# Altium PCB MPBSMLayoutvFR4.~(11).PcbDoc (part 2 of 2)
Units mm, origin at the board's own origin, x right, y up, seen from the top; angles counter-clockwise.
Board outline 131.7 x 110.39 mm, 4 copper layers (Top Layer, Power, GroundPlane, Bottom Layer), stack 2.286 mm thick; 156 components, 77 nets, 429 pads, 117 vias.
Unrouted connection lines stored in the file: 25.
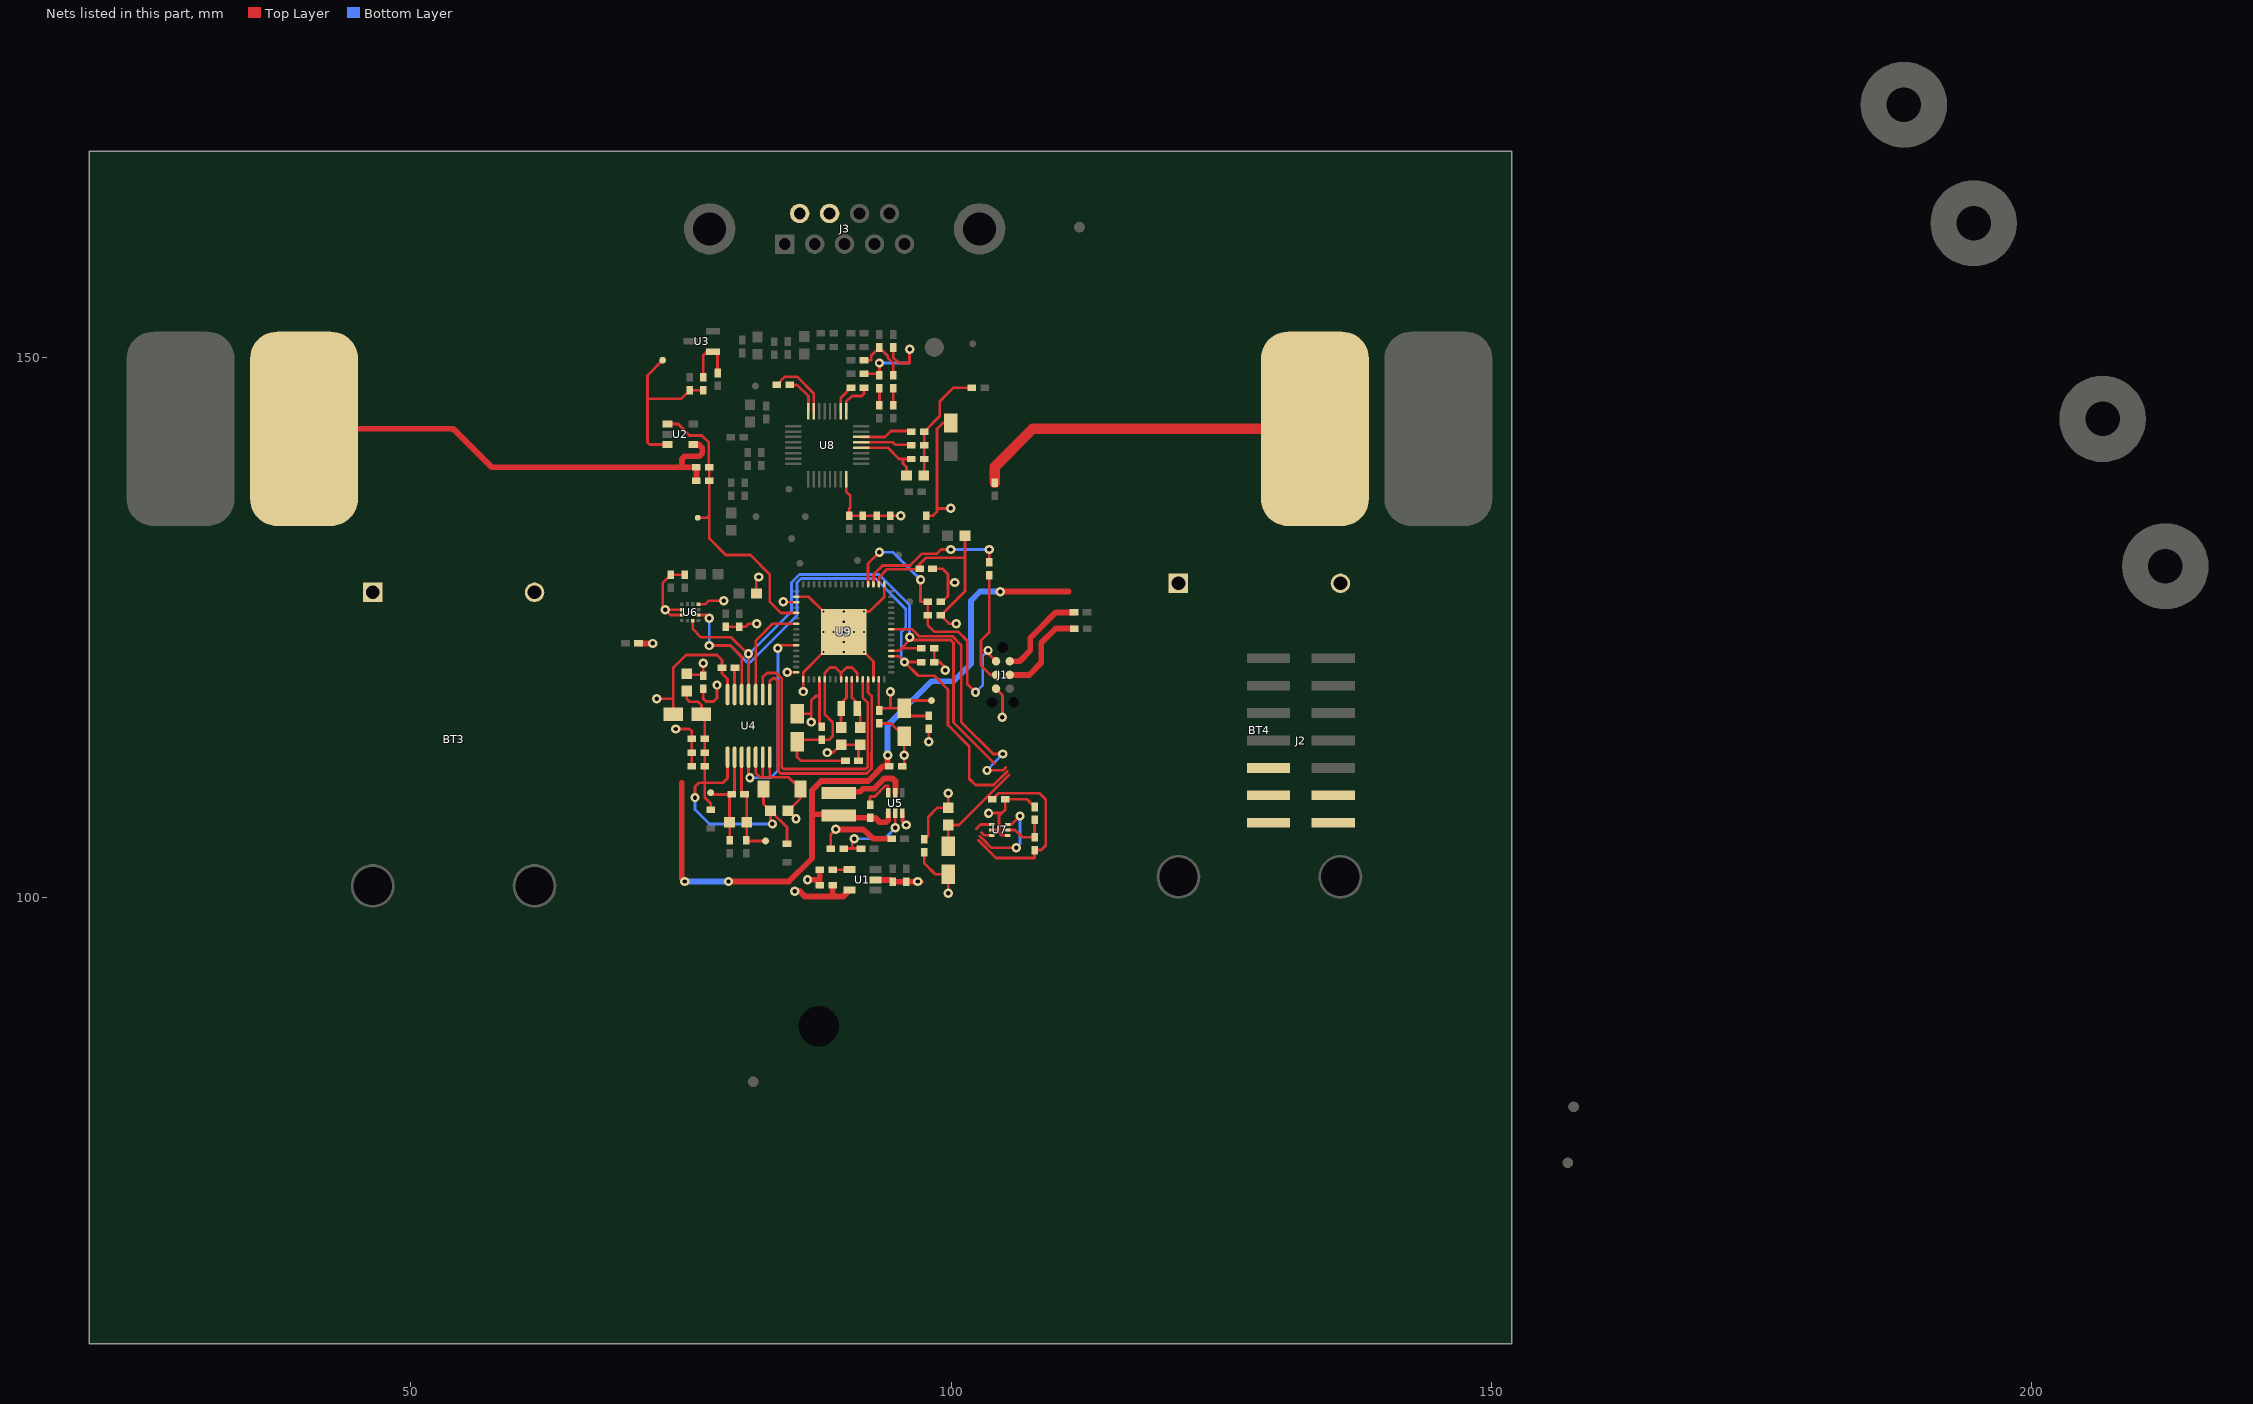
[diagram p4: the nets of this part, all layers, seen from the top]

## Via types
v1: diameter 0.864, hole 0.406, Top Layer to Bottom Layer, 104 vias
v2: diameter 0.5, hole 0.2, Top Layer to Bottom Layer, 13 vias

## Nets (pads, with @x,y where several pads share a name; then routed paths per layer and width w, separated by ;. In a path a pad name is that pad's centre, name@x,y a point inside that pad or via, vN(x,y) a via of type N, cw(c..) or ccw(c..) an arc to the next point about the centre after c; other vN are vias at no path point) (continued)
BOOST_INPUT: BT3.1 BT4.1 C34.1 L7.1 R16.1 U5.1 | length 73.3
  Top Layer w0.254: L7.1@89.586,107.681 L7.1@89.595,107.672 ; v1(94.132,113.132) v1@94.294,112.97
  Top Layer w0.5: 75.082,110.592 75.082,101.702 v1(75.336,101.448)
  Top Layer w0.54: v1(79.4,101.448) 84.988,101.448 87.122,103.581 87.122,109.906 87.96,110.744 92.304,110.744 93.675,112.116 C34.1@94.294,112.116 ; 87.122,107.696 L7.1@89.586,107.681 ; L7.1@89.806,107.35 R16.1@92.507,107.35 92.992,107.35 93.408,106.934 93.98,106.934 94.194,107.148 U5.1@94.194,107.762 ; C34.1@94.132,112.278 v1(94.132,113.132) ; v1(104.546,128.287) 110.895,128.287
  Bottom Layer w0.54: v1(75.336,101.448) v1(79.4,101.448) ; v1(94.132,113.132) 94.132,115.926 98.196,119.99 100.228,119.99 101.845,121.606 101.845,127.448 102.684,128.287 v1(104.546,128.287)
DVCC: 1.1 C1.1 C5.1 C6.1 C10.1 C14.1 C18.1 L1.1 L2.1 L3.1 L5.1 R1.1 R6.2 R31.1 R32.1 U1.5 U9.18 U9.35 U9.48 U9.63 | length 53
  Top Layer w0.254: L1.1@75.336,120.59 76.914,120.59 C10.1@76.938,120.613 ; C10.1@77.064,120.488 v1(77.064,121.666) ; L3.1@81.978,128.118 81.978,129.426 v1(82.194,129.642) ; v1@84.524,127.312 U9.35@85.668,127.312 ; v1(84.85,120.812) U9.48@85.668,120.812 ; U9.63@93.319,120.162 93.319,117.339 C6.1@93.37,117.288 ; U9.18@93.319,128.962 93.365,129.008 93.365,129.637 94.084,130.356 97.04,130.356 C18.1@97.088,130.404 97.088,130.82 97.688,131.42 101.244,131.42 ; C6.1@93.562,117.48 C1.1@95.656,117.48 ; 94.39,117.483 v1(94.39,119.027) ; C14.1@97.513,105.35 97.892,105.728 97.892,107.414 98.763,108.286 L2.1@99.753,108.286 v1(99.753,109.621) ; R1.1@97.942,116.78 96.356,116.78 C1.1@95.656,117.48 ; 1.1@98.196,118.212 96.388,118.212 C1.1@95.656,117.48 ; R32.1@98.45,123.038 R31.1@98.45,121.768 98.958,121.768 99.466,121.26 v1(99.466,121.006) ; v1(100.482,125.324) 99.812,125.324 R6.2@99.05,126.086 101.282,128.318 L5.1@101.282,133.452
  Top Layer w0.54: v1(85.522,100.559) v1@85.928,100.559 ; 85.954,100.584 86.462,100.076 89.048,100.076 ; C5.1@89.048,101.092 89.048,100.076 ; U1.5@90.596,100.65 90.022,100.076 89.048,100.076
  other v1: 84.48,127.356
EL_GSR1: C26.2 J3.7 R10.1 TP2.1 U2.4 | length 43.3
  Top Layer w0.254: U2.4@76.144,141.9 76.656,141.9
  Top Layer w0.54: TP2.1@40.107,143.358 53.924,143.358 57.48,139.802 R10.1@76.422,139.802 C26.2@76.422,138.532 ; 75.082,139.852 75.082,140.564 75.336,140.818 76.722,140.818 76.976,141.072 76.976,141.58 76.656,141.9
EL_GSR2: J3.6 R9.2 TP1.1 | length 32.6
  Top Layer w1: R9.2@104.038,138.37 104.038,139.827 107.569,143.358 TP1.1@133.68,143.358
GND: BT3.2 BT4.2 C1.2 C3.2 C4.2 C5.2 C6.2 C8.2 C9.2 C10.2 C11.2 C12.2 C13.2 C14.2 C15.2 C16.2 C17.2 C18.2 C19.2 C20.2 C21.2 C25.2 C27.2 C28.2 C29.1 C32.2 C33.2 C34.2 C35.2 C36.2 C37.2 C38.2 C41.2 C42.2 C58.2 C59.2 J1.6 J2.6 R2.1 R3.1 R17.1 U1.2 U4.5 U4.6 U4.7 U4.14 U5.3 U6.4 U6.8 U6.9 U7.2 U7.4 U8.24 U9.17 U9.34 U9.49 U9.62 U9.65 | length 145.9
  Top Layer w0.254: v1(72.746,118.364) 74.29,118.364 ; C9.2@74.29,116.942 74.29,118.364 ; v1(74.524,115.57) 75.794,115.57 76.006,115.357 C27.2@76.006,114.656 C11.2@76.006,113.386 C28.2@76.006,112.116 ; U6.9@75.069,126.111 74.041,126.111 v1(73.558,126.594) ; U6.8@75.069,126.611 73.575,126.611 v1(73.558,126.594) ; C37.2@75.336,129.847 C16.2@74.066,129.847 73.304,129.085 73.304,126.848 v1(73.558,126.594) ; U6.4@76.619,127.111 77.223,127.111 77.545,127.433 v1(78.965,127.433) ; C10.2@77.064,119.288 77.064,118.364 77.318,118.11 78.022,118.11 78.334,118.422 v1(78.334,119.634) ; C36.2@79.146,125.024 C17.2@80.416,125.024 80.972,125.024 81.272,125.324 v1(82.017,125.324) ; U4.14@79.311,118.764 79.311,120.193 78.8,120.704 C29.1@78.8,121.26 78.8,121.961 78.334,122.428 75.459,122.428 74.29,121.26 74.29,118.364 ; U4.5@81.911,112.964 81.911,111.484 82.296,111.1 83.21,111.1 ; 82.561,111.137 U4.6@82.561,112.964 ; U4.7@83.211,112.964 83.21,111.1 ; v1(85.645,107.266) 85.62,107.266 C33.2@84.895,107.991 86.049,109.145 C32.2@86.049,110.023 84.972,111.1 83.21,111.1 ; U9.34@85.668,127.812 86.818,127.812 v2(88.193,126.437) v2(90.068,124.562) ; v1(86.317,119.033) U9.49@86.317,120.162 86.317,120.811 v2(88.193,122.687) v2(90.068,124.562) ; v1(86.716,101.6) v1@86.728,101.613 ; v1(88.544,113.386) 89.09,113.386 89.814,114.11 C58.2@91.592,114.11 ; R17.1@88.868,104.496 88.868,105.812 v1(89.33,106.274) ; U8.24@90.294,138.704 90.294,137.544 90.676,137.162 90.676,136.099 90.576,135.999 C42.2@90.576,135.322 C41.2@91.846,135.322 C19.2@93.116,135.322 C20.2@94.386,135.322 v1@95.291,135.322 ; R2.1@91.43,112.624 C58.2@91.43,113.948 ; U9.62@92.819,120.162 92.819,121.811 v2(91.943,122.687) v2(90.068,124.562) ; C6.2@93.37,115.888 C6.2@93.37,116.088 94.448,116.088 C1.2@95.656,114.88 95.675,114.861 v1(95.675,113.132) 95.675,112.296 C34.2@95.494,112.116 C34.2@95.656,111.954 ; U9.17@93.819,128.962 93.819,127.805 92.451,126.437 v2(91.943,126.437) v2(90.068,124.562) ; C3.2@94.422,101.6 C3.2@94.594,101.428 ; v1(96.926,101.448) 96.926,101.194 v1@97.16,101.428 ; C14.2@97.513,104.15 97.513,103.147 98.538,102.122 C12.2@99.753,102.122 v1(99.753,100.374) ; C21.2@97.688,135.322 98.339,135.322 98.704,135.687 98.704,143.358 99.242,143.896 C15.2@99.974,143.896 C15.2@99.974,144.374 ; C18.2@98.288,130.404 99.212,130.404 99.72,129.896 99.72,129.134 ; 98.704,135.992 v1(99.974,135.992) ; C25.2@99.05,127.356 99.212,127.356 99.72,127.864 99.72,129.134 ; v1(100.355,129.134) 99.72,129.134 ; v1(103.475,107.783) 104.719,107.783 ; U7.2@103.754,106.221 104.423,106.221 ; J1.6@104.165,119.304 104.775,118.694 104.775,116.688 v1(104.75,116.662) ; U7.4@105.254,105.721 104.699,105.721 104.449,105.971 104.449,107.512 104.719,107.783 ; C38.2@107.731,108.352 107.015,109.068 C13.2@105.029,109.068 105.029,108.093 104.719,107.783
  Top Layer w0.354: U5.3@95.494,107.762 95.494,107.046 v1(95.86,106.68)
  Top Layer w0.54: R3.1@71.069,123.489 v1(72.371,123.489) ; v1@86.728,101.613 87.848,101.613 ; C5.2@87.848,101.092 87.848,101.613 ; C8.2@87.848,102.54 87.848,101.613 ; v1(89.33,106.274) 90.646,106.274 91.846,106.274 92.812,105.41 C35.2@94.548,105.41 ; U1.2@92.996,101.6 C3.2@94.422,101.6 ; C3.2@94.594,101.428 C4.2@95.864,101.428 v1@97.16,101.428
  other v1: 95.352,135.322
  other v2: 90.068,122.687 90.068,123.624 88.193,124.562 89.131,124.562 91.006,124.562 91.943,124.562 90.068,125.499 90.068,126.437
GSR_ANALOG_OUTPUT: 2.1 C26.1 R10.2 U2.1 U9.37 | length 26.9
  Top Layer w0.254: U2.1@73.744,143.8 74.751,143.8 75.802,142.748 76.92,142.748 77.58,142.088 77.58,140.14 77.622,140.098 R10.2@77.622,139.802 C26.1@77.622,138.532 77.622,135.23 ; 2.1@76.556,135.128 77.521,135.128 ; 77.521,135.23 77.622,135.23 ; U9.37@85.668,126.312 84.254,126.312 83.21,127.356 83.21,129.896 81.432,131.674 79.146,131.674 77.622,133.198 77.622,135.23
JTAG_TCK: J1.4 J2.4 R7.1 | length 10.4
  Top Layer w0.254: R7.1@103.53,129.804 103.53,124.511 102.768,123.749 102.768,121.463 103.657,120.574 J1.4@104.165,120.574
JTAG_TDO/TDI: C25.1 J1.2 J2.2 R6.1 U9.20 | length 28.1
  Top Layer w0.254: U9.20@92.319,128.962 92.319,130.876 v1(93.37,131.928) ; v1(97.18,129.388) 97.18,127.356 C25.1@97.85,127.356 R6.1@97.85,126.086 97.85,125.162 98.45,124.562 100.677,124.562 101.498,123.74 101.498,119.736 v1(102.26,118.974) ; v1(103.429,122.843) 103.429,122.58 J1.2@104.165,121.844
  Bottom Layer w0.254: v1(93.37,131.928) 94.64,131.928 v1(97.18,129.388) ; v1(102.26,118.974) 102.946,119.659 102.946,122.36 v1(103.429,122.843)
JTAG_TEST/SBWTCK: R7.2 U9.19 | length 13.7
  Top Layer w0.254: U9.19@92.819,128.962 92.819,129.852 93.676,130.71 96.216,130.71 97.307,131.801 98.703,131.801 99.084,132.182 v1(99.974,132.182) ; R7.2@103.53,131.004 v1(103.53,132.182)
  Bottom Layer w0.254: v1(99.974,132.182) v1(103.53,132.182)
JTAG_VCC_TARGET_IN: J1.3 J2.3 R5.1 | length 8.8
  Top Layer w0.54: J1.3@105.435,120.574 107.239,120.574 108.356,121.691 108.356,122.707 108.356,123.546 109.672,124.861 R5.1@111.408,124.861
JTAG_VCC_TOOL_OUT: J1.1 J2.1 R4.1 | length 8.5
  Top Layer w0.54: J1.1@105.435,121.844 106.35,121.844 107.34,122.834 107.34,124.003 109.703,126.365 R4.1@111.389,126.365
MSP_AVCC: C2.1 C7.1 R1.2 U9.52 | length 9.3
  Top Layer w0.254: C2.1@86.07,116.972 87.05,116.972 ; v1(87.05,116.21) 87.05,116.972 ; C7.1@87.818,115.982 87.818,118.618 ; U9.52@87.818,120.162 87.818,118.618 ; v1(97.942,114.402) R1.2@97.942,115.58 ; 87.05,116.972 87.05,118.191 87.478,118.618 87.818,118.618
MSP_AVSS: C2.2 C7.2 R2.2 U9.53 U9.56 U9.59 | length 20.5
  Top Layer w0.254: C2.2@85.75,114.372 85.75,112.979 86.106,112.624 R2.2@90.23,112.624 ; C2.2@85.942,114.564 C7.2@88.036,114.564 88.706,114.564 89.052,114.91 89.052,116.18 88.318,116.914 U9.53@88.318,120.162 88.318,120.779 88.798,121.26 89.306,121.26 89.81,120.756 ; U9.56@89.818,120.162 89.818,120.756 90.322,121.26 90.83,121.26 91.319,120.771 U9.59@91.319,120.162
MSP_LFXIN: C59.1 U9.57 Y1.1 | length 4.1
  Top Layer w0.254: C59.1@89.814,115.71 89.814,117.438 Y1.1@89.826,117.45 ; Y1.1@89.826,117.97 90.318,118.462 U9.57@90.318,120.162
MSP_LFXOUT: C58.1 U9.58 Y1.2 | length 4.3
  Top Layer w0.254: U9.58@90.819,120.162 90.819,118.477 Y1.2@91.326,117.97 ; Y1.2@91.326,117.45 91.592,117.184 C58.1@91.592,115.71
MSP_P1.0_INT: U4.10 U9.39 | length 9.4
  Top Layer w0.254: U4.10@81.911,118.764 81.911,123.749 ; 81.927,123.749 83.49,125.312 U9.39@85.668,125.312
MSP_P2.7_INT: U7.3 U9.9 | length 24.2
  Top Layer w0.254: U9.9@94.468,124.812 96.392,124.812 97.05,124.154 100.128,124.154 100.936,123.346 100.936,116.234 103.911,113.259 v1(104.775,113.259) ; 102.816,105.989 103.084,105.721 U7.3@103.754,105.721 ; v1@103.335,111.743 104.796,111.743 105.064,112.011
  Bottom Layer w0.254: v1(103.327,111.735) v1(104.775,113.259)
MSP_P4.0_INT: U4.9 U9.60 | length 28.4
  Top Layer w0.254: U4.9@82.561,118.764 82.561,120.356 82.956,120.752 83.823,120.752 84.326,120.248 84.326,112.016 84.48,111.862 92.1,111.862 92.285,112.046 92.285,113.506 92.294,113.516 92.294,114.704 92.285,114.713 92.285,115.106 92.294,115.116 92.294,116.304 92.285,116.313 92.285,118.027 91.819,118.493 U9.60@91.819,120.162
MSP_P4.1_INT: U4.8 U9.61 | length 27.8
  Top Layer w0.254: U4.8@83.211,118.764 83.211,119.99 83.464,120.244 83.718,120.244 83.972,119.99 83.972,111.718 84.236,111.454 92.2,111.454 ; 92.2,111.461 92.639,111.9 92.639,113.36 92.648,113.369 92.648,118.612 92.319,118.942 U9.61@92.319,120.162
MSP_P9.3_OUT: U4.4 U9.43 | length 18
  Top Layer w0.254: U4.4@81.261,112.964 81.261,111.169 v1(81.382,111.049) ; v1(83.972,123.038) 84.246,123.312 U9.43@85.668,123.312
  Bottom Layer w0.254: v1(81.382,111.049) 83.304,111.049 83.972,111.718 v1(83.972,123.038)
MSP_UCB0SCL_TMP103_SCL_RF430CL330HCPW_SCL: R32.2 U4.11 U6.12 U7.1 U9.5 | length 56.8
  Top Layer w0.254: U6.12@76.094,125.586 76.094,124.82 76.86,124.054 79.654,124.054 v1@81.211,122.497 ; U4.11@81.261,118.764 v1@81.261,122.447 ; U9.5@94.468,122.812 95.176,122.812 95.402,123.038 ; v1(96.164,124.054) v1@96.164,123.8 ; R32.2@97.088,123.038 95.402,123.038 ; 102.365,106.343 102.743,106.721 U7.1@103.754,106.721 ; 104.018,112.365 103.836,112.547 100.228,116.18 100.228,123.546 99.974,123.8 v1@96.164,123.8 ; 95.402,123.038 v1@96.164,123.8
  Bottom Layer w0.254: v1(81.252,122.539) 81.261,122.531 81.261,122.447 85.242,126.428 85.242,129.134 85.975,129.866 93.34,129.866 96.164,127.042 v1(96.164,124.054)
MSP_UCB0SDA_TMP103_SDA_RF430CL330HCPW_SDA: R31.2 U4.12 U6.2 U7.6 U9.4 | length 70.6
  Top Layer w0.254: U6.2@76.619,126.111 77.343,126.111 v1(77.622,125.832) ; v1(77.622,123.292) 79.568,123.292 80.627,122.233 80.627,118.78 U4.12@80.611,118.764 ; U9.4@94.468,122.312 95.148,122.312 v1(95.692,121.768) ; R31.2@97.25,121.768 v1(95.692,121.768) ; 102.669,105.635 102.972,105.332 102.98,105.332 103.742,104.57 v1(106.028,104.57) ; 105.211,111.657 103.943,110.388 102.26,110.388 101.689,110.96 101.689,113.957 99.72,115.926 99.72,119.228 98.45,120.498 96.962,120.498 v1(95.692,121.768) ; U7.6@105.254,106.721 105.588,106.721 v1(106.383,107.516)
  Bottom Layer w0.254: v1(77.622,125.832) v1(77.622,123.292) 79.568,123.292 81.092,121.768 81.432,121.768 85.75,126.086 85.75,129.134 86.129,129.512 92.992,129.512 95.81,126.694 95.81,124.97 95.402,124.562 95.402,122.058 v1(95.692,121.768) ; v1(106.028,104.57) 106.383,104.925 v1(106.383,107.516)
Net3_1: 3.1 R11.1 R12.2 U2.3 | length 15.6
  Top Layer w0.254: 71.896,146.152 75.033,146.152 R12.2@75.799,146.917 R11.1@77.069,146.917 ; 3.1@73.304,149.708 71.896,148.3 71.896,142.088 72.084,141.9 U2.3@73.744,141.9
Net4_1: 4.1 C30.1 C31.1 R13.1 U4.2 | length 9.9
  Top Layer w0.254: 4.1@77.745,109.676 77.906,109.515 C31.1@79.685,109.515 ; R13.1@79.523,105.255 79.523,106.903 C30.1@79.485,106.941 79.485,109.315 C31.1@79.685,109.515 ; U4.2@79.961,112.964 79.961,109.791 C31.1@79.685,109.515
Net5_1: 5.1 C30.2 C31.2 R14.1 U4.3 | length 9.9
  Top Layer w0.254: U4.3@80.611,112.964 80.611,109.788 C31.2@80.885,109.515 81.085,109.315 C30.2@81.085,106.941 81.085,105.293 81.181,105.197 5.1@83.079,105.197
NetC8_1: C8.1 U1.4 | length 1.6
  Top Layer w0.254: C8.1@89.043,102.54 89.053,102.55 U1.4@90.596,102.55
NetC29_2: C29.2 U4.13 | length 2.5
  Top Layer w0.254: U4.13@79.961,118.764 79.961,121.22 C29.2@80,121.26
NetC38_1: C38.1 R18.1 U7.5 | length 4.3
  Top Layer w0.254: U7.5@105.254,106.221 105.926,106.221 106.589,105.558 R18.1@107.731,105.558 C38.1@107.731,107.152
NetC43_1: C43.1 R19.2 R20.2 R21.2 R22.1 | length 10.9
  Top Layer w0.254: C43.1@97.526,139.094 R20.2@97.526,140.564 R21.2@97.526,141.834 97.526,141.876 R19.2@97.526,143.104 98.958,144.536 98.958,145.898 99.678,146.618 100.228,147.168 R22.1@101.914,147.168
NetC43_2: C43.2 R20.1 U8.28 | length 6.7
  Top Layer w0.254: U8.28@91.694,141.603 94.147,141.603 95.186,140.564 95.555,140.564 ; C43.2@95.872,139.04 95.872,139.818 95.555,140.135 95.555,140.564 ; R20.1@96.326,140.564 95.555,140.564
NetC45_1: C45.1 U8.2 | length 2.6
  Top Layer w0.254: U8.2@89.794,145.003 89.794,146.224 C45.1@90.738,147.168
NetC45_2: C45.2 U8.1 | length 3.4
  Top Layer w0.254: U8.1@90.294,145.003 90.294,145.87 90.83,146.406 91.732,146.406 91.938,146.612 C45.2@91.938,147.168
NetC46_2: C46.2 C48.2 C49.2 | length 10.4
  Top Layer w0.254: C46.2@91.938,148.45 C49.2@93.242,148.45 ; C49.2@93.37,148.322 v1(93.37,149.454) ; C48.2@94.64,150.886 94.646,150.88 94.646,149.967 95.16,149.454 96.164,149.454 v1(96.164,150.724)
  Bottom Layer w0.254: v1(93.37,149.454) 96.164,149.454 v1(96.164,150.724)
NetC47_1: C47.1 U8.8 | length 3.5
  Top Layer w0.254: C47.1@85.08,147.422 85.75,147.422 86.794,146.378 U8.8@86.794,145.003
NetC47_2: C47.2 U8.7 | length 6
  Top Layer w0.254: C47.2@83.88,147.422 84.642,148.184 85.75,148.184 87.294,146.64 U8.7@87.294,145.003
NetC49_1: C49.1 R26.1 | length 1.6
  Top Layer w0.254: R26.1@93.37,145.528 C49.1@93.37,147.122
NetC52_2: C52.2 C53.2 C54.2 | length 5.3
  Top Layer w0.254: C54.2@91.938,149.708 92.608,149.708 92.608,150.124 C52.2@93.37,150.886 94.132,150.124 94.132,149.962 94.64,149.454 C53.2@94.64,148.322
NetC53_1: C53.1 R27.1 | length 1.6
  Top Layer w0.254: R27.1@94.64,145.528 C53.1@94.64,147.122
NetL7_2: L7.2 U5.5 | length 5.5
  Top Layer w0.254: 92.913,110.033 92.913,110.084
  Top Layer w0.54: L7.2@91.034,109.752 91.566,109.752 91.846,110.033 92.913,110.033 ; 92.913,110.084 93.494,110.664 93.828,110.998 94.59,110.998 94.844,110.744 U5.5@94.844,109.662
NetR8_1: R8.1 R11.2 U3.1 | length 5.5
  Top Layer w0.254: R11.2@77.069,148.117 77.069,150.17 77.434,150.536 78.384,150.536 R8.1@78.384,148.53
NetR15_1: R15.1 R17.2 U5.2 | length 8.1
  Top Layer w0.254: R17.2@90.068,104.496 90.865,104.496 ; v1(91.034,105.41) 90.865,105.242 90.865,104.496 ; R15.1@91.662,104.496 90.865,104.496 ; v1(94.844,106.426) U5.2@94.844,107.762
  Bottom Layer w0.254: v1(91.034,105.41) 93.828,105.41 v1(94.844,106.426)
NetR16_2: R16.2 U5.6 | length 3.5
  Top Layer w0.254: R16.2@92.507,108.55 92.507,109.271 92.558,109.322 92.939,109.322 93.944,110.327 94.183,110.327 94.183,109.672 U5.6@94.194,109.662
NetR19_1: R19.1 U8.30 | length 4.9
  Top Layer w0.254: U8.30@91.694,142.603 93.886,142.603 94.428,143.146 R19.1@96.326,143.146
NetR21_1: R21.1 U8.29 | length 4.7
  Top Layer w0.254: U8.29@91.694,142.103 94.625,142.103 94.852,141.876 R21.1@96.326,141.876
RF430_DVCC: C9.1 C11.1 C27.1 C28.1 C32.1 C33.1 D1.1 D2.1 L1.2 U4.1 | length 34
  Top Layer w0.254: 75.54,118.512 75.54,118.338 75.786,118.092 76.574,118.092 76.89,117.775 C9.1@76.89,116.942 C9.1@77.114,117.166 ; v1(76.302,109.22) 76.302,110.236 76.657,110.592 77.201,110.592 ; C28.1@77.206,112.116 C11.1@77.206,113.386 C27.1@77.206,114.656 C9.1@77.206,116.626 ; C28.1@77.298,112.024 77.201,111.926 77.201,110.592 ; D1.1@77.745,108.079 77.745,108.691 77.201,109.235 77.201,110.592 ; U4.1@79.311,112.964 79.311,111.01 78.892,110.592 77.201,110.592 ; C32.1@82.649,110.023 82.649,108.637 C33.1@83.295,107.991 ; v1(83.464,106.782) 83.295,106.951 C33.1@83.295,107.991 ; D2.1@84.811,104.989 84.811,106.475 C33.1@83.295,107.991
  Bottom Layer w0.254: v1(76.302,109.22) 76.302,108.102 77.622,106.782 v1(83.464,106.782)
TMP_DVCC: C12.1 C13.1 L2.2 R18.2 | length 27
  Top Layer w0.254: C12.1@99.753,104.722 L2.2@99.753,106.686 100.74,106.686 105.358,111.303 ; 102.522,105.281 104.173,103.63 107.731,103.63 R18.2@107.731,104.358 108.355,104.358 108.766,104.768 108.766,109.049 108.197,109.618 104.379,109.618 C13.1@103.829,109.068
pads on no net: BT3.3 BT3.4 BT4.3 BT4.4 FID1.1 FID2.1 FID3.1 H1.0 H2.0 H3.0 H4.0 H5.1 H6.1 H7.1 H8.1 H9.0 H10.0 H11.0 H12.0 J1.5 J1.MH1 J1.MH2 J1.MH3 J2.5 J2.7 J2.8 J2.9 J2.10 J2.11 J2.12 J2.13 J2.14 J3.3 J3.5 J3.8 J3.9 U3.3 U6.10 U8.17 U9.1 U9.2 U9.3 U9.6 U9.7 U9.8 U9.10 U9.11 U9.12 U9.13 U9.15 U9.21 U9.22 U9.23 U9.24 U9.36 U9.40 U9.41 U9.42 U9.44 U9.45 U9.46 U9.47 U9.50 U9.51 U9.54 U9.55 U9.64
copper on no net: | length 0.5
  Top Layer w0.254: 104.496,124.206 v1(104.496,124.714)

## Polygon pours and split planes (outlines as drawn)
DVCC on Power (split plane): 102.385,142.288 102.385,131.727 101.75,131.092 78.641,131.092 78.006,131.727 78.006,133.144 79.2,134.338 93.116,134.338 93.166,134.348 93.208,134.376 98.288,139.456 98.316,139.498 98.326,139.548 98.326,142.796 98.735,143.205 101.468,143.205
DVCC on Power (split plane): 87.561,117.065 87.907,116.61 87.907,112.624 87.917,112.574 87.945,112.532 87.987,112.504 88.036,112.494 96.002,112.494 96.052,112.504 96.094,112.532 97.018,113.456 97.046,113.498 97.056,113.548 97.056,115.796 98.819,115.796 98.819,115.57 98.819,113.937 98.359,113.477 97.081,112.2 96.619,111.737 86.778,111.737 86.134,112.41 86.134,116.653 86.549,117.089
DVCC on Power (split plane): 90.701,154.534 90.66,146.998 81.941,147.043 81.94,147.043 81.916,147.038 81.891,147.033 81.87,147.019 81.849,147.006 81.849,147.005 81.835,146.984 81.821,146.964 81.821,146.963 81.816,146.939 81.811,146.914 81.811,143.104 81.821,143.054 81.849,143.012 81.891,142.984 81.94,142.974 86.637,142.974 86.637,141.201 83.464,141.201 83.415,141.191 83.373,141.163 83.345,141.121 83.335,141.072 83.335,135.359 77.193,135.359 77.193,139.09 77.183,139.14 77.155,139.182 74.958,141.379 74.958,145.59 77.975,148.607 79.114,148.607 79.138,148.612 79.163,148.616 79.163,148.617 79.184,148.631 79.205,148.644 79.205,148.645 79.219,148.665 79.233,148.686 79.233,148.687 79.238,148.711 79.243,148.736 79.275,154.658 90.701,154.658
DVCC on Power (split plane): 151.407,158.471 151.407,59.159 20.729,59.159 20.729,168.527 151.407,168.527
ADS_AVSS on GroundPlane (split plane): 151.407,158.471 151.407,128.806 102.136,128.806 102.136,137.008 102.126,137.057 102.098,137.099 102.056,137.127 102.006,137.137 98.958,137.137 98.909,137.127 98.867,137.099 98.839,137.057 98.829,137.008 98.829,135.765 96.497,135.765 96.497,136.398 96.487,136.448 96.459,136.49 96.417,136.518 96.368,136.527 89.428,136.527 89.413,136.524 89.398,136.524 89.389,136.52 89.379,136.518 89.366,136.509 89.352,136.503 77.682,127.993 20.729,128.018 20.729,168.527 151.407,168.527
GND on GroundPlane (split plane): 101.877,128.676 101.887,128.627 101.915,128.585 101.957,128.557 102.006,128.547 151.407,128.547 151.407,59.159 20.729,59.159 20.729,127.759 77.724,127.734 77.774,127.744 77.816,127.772 77.819,127.776 77.835,127.784 89.471,136.269 96.238,136.269 96.238,135.636 96.248,135.586 96.276,135.544 96.318,135.516 96.368,135.507 98.958,135.507 99.008,135.516 99.05,135.544 99.078,135.586 99.088,135.636 99.088,136.878 101.877,136.878

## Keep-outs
Keep-Out Layer:
  text ".Layer_Name" at 157.226,108.306 h1.52

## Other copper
Top Layer:
  text ".Layer_Name" at 157.226,156.566 h1.52
Bottom Layer:
  text ".Layer_Name" at 157.226,154.026 h1.52
  text "SVN:" at 49.695,114.91 h1.52 r90
  text ".VersionControl_RevNumber" at 49.695,107.823 h1.52 r90
  text "UL94V-0" at 55.728,69.774 h1.52 r90
Power (plane layer: these items are gaps in the copper):
  rectangle: 74.828,69.952 100.228,99.67
  lines w0.254: 98.948,115.57 98.948,115.926 ; 98.948,115.926 98.545,115.926 96.926,115.926 96.926,113.548 96.002,112.624 88.256,112.624 88.036,112.624 88.036,116.654 87.627,117.193 86.494,117.219 86.004,116.705 86.004,112.358 86.722,111.608 92.19,111.608 96.672,111.608 97.173,112.108 98.45,113.386 98.948,113.884 98.948,115.926 ; 74.828,141.326 77.064,139.09 77.064,135.23 81.237,135.23 83.464,135.23 83.464,141.072 86.766,141.072 86.766,143.104 81.94,143.104 81.94,146.914 90.788,146.868 90.83,154.534 90.83,154.788 79.146,154.788 79.114,148.736 77.921,148.736 74.828,145.644 74.828,141.326 ; 77.876,131.674 77.876,133.198 79.146,134.468 93.116,134.468 98.196,139.548 98.196,142.85 98.681,143.334 101.522,143.334 102.514,142.342 102.514,131.674 101.803,130.962 78.588,130.962 77.876,131.674
GroundPlane (plane layer: these items are gaps in the copper):
  rectangle: 74.828,69.952 100.228,99.67
  lines w0.254: 20.091,127.889 77.724,127.864 ; 77.758,127.888 89.428,136.398 96.368,136.398 96.368,135.636 98.958,135.636 98.958,137.008 102.006,137.008 102.006,128.676 151.765,128.676

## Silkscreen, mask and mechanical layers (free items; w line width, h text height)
Top Overlay:
  region: 96.368,77.724 96.368,85.344 93.828,85.344 93.828,77.724
  lines w1: 73.914,70.891 101.041,70.891 101.041,98.222 73.914,98.222 73.914,70.891
  lines w2: 20.98,133.325 44.78,133.325 150.292,133.325 ; 48.971,60.96 48.971,132.918 48.971,167.716 ; 125.679,61.646 125.679,167.157
  text "GSR" at 130.099,153.289 h4
  text "ECG" at 141.478,153.238 h4
  text "ECG" at 24.74,152.806 h4
  text "GSR" at 37.389,152.756 h4
  text "GND" at 46.634,131.318 h1.02
  text "VCC" at 60.147,129.845 h1.02
  text ".Layer_Name" at 157.226,128.626 h1.52
  text "JTAG" at 106.782,126.009 h1.02
  text "BAT" at 110.592,122.987 h1.02
  text "VCC" at 62.027,121.361 h1.02
  text "GND" at 46.888,121.158 h1.02
  text "FOR DEMO PURPOSES ONLY" at 76.53,94.259 h1.02
  text "MPBSM" at 80.112,91.44 h1.02
  text "REV A" at 80.112,89.916 h1.02
  text "TI" at 92.202,87.884 h1.52
  text "©" at 94.844,87.63 h2.67
  text ".CopyrightYear" at 85.192,77.724 h1.52
  text "MADE IN U.S." at 78.842,75.438 h1.52
  text "NFC Antenna" at 80.594,68.504 h2
  text "-" at 50.952,67.666 h1.52 r90
  text "Place phone here" at 52.959,62.84 h10
Bottom Overlay:
  text ".Layer_Name" at 157.226,126.086 h1.52
Top Paste:
  text ".Layer_Name" at 157.226,123.546 h1.52
Bottom Paste:
  text ".Layer_Name" at 157.226,121.006 h1.52
Top Solder:
  text ".Layer_Name" at 157.226,118.466 h1.52
  text ".Layer_Name" at 157.226,115.926 h1.52
Bottom Solder:
  text ".Layer_Name" at 157.226,113.386 h1.52
Drill Guide:
  text ".Layer_Name" at 157.226,110.846 h1.52
M1 Board Outline:
  lines w0.254: 75.336,58.257 101.625,58.257
  text ".Layer_Name" at 157.226,151.486 h1.52
M2 Board Dimensions:
  rectangle: 17.577,32.982 20.752,36.157
  rectangle: 20.752,29.807 30.277,32.982
  lines w0.178: 17.577,32.982 42.977,32.982 ; 20.752,29.807 20.752,36.157 ; 23.927,29.807 23.927,36.157 ; 30.277,29.807 30.277,36.157 ; 36.627,29.807 36.627,36.157 ; 17.577,29.807 42.977,29.807 42.977,36.157 17.577,36.157 17.577,29.807
  text ".Layer_Name" at 18.034,37.338 h1.52
M3 3D STEP Top:
  text ".Layer_Name" at 157.226,148.946 h1.52
M4 3D STEP Bottom:
  text ".Layer_Name" at 157.226,146.406 h1.52
M5 Assembly Top:
  lines w0.254: 10.16,16.607 177.8,16.607 ; 10.16,21.772 177.851,21.772 ; 10.16,26.937 10.16,11.443 111.887,11.443 177.851,11.443 177.851,26.937 10.173,26.937 10.173,11.443 50.19,11.443 ; 72.771,11.443 72.771,26.937 ; 104.953,21.772 104.953,26.937 ; 126.289,21.772 126.289,26.937 ; 142.088,11.278 142.088,16.43
  text "COMPONENTS MARKED 'DNP' SHOULD NOT BE POPULATED." at 46.876,32.144 h1.52
  text "ASSEMBLY VARIANT:" at 46.863,29.21 h1.52
  text ".VariantName" at 73.177,29.21 h1.52
  text "PCB VIEWED FROM TOP SIDE" at 11.773,23.58 h1.52
  text "BOARD #:" at 74.676,23.58 h1.52
  text ".PRJ_Number" at 88.532,23.58 h1.52
  text "REV:" at 109.982,23.58 h1.52
  text ".PCB_Rev" at 117.386,23.58 h1.52
  text "SVN REV:" at 131.267,23.58 h1.52
  text ".VersionControl_RevNumber" at 144.12,23.58 h1.52
  text "IGNORE ->" at 11.773,18.428 h1.52
  text "PLOT NAME =" at 11.773,13.199 h1.52
  text ".plot_File_Name" at 32.233,13.199 h1.52
  text "GENERATED    :" at 74.727,13.199 h1.52
  text ".Print_Date" at 96.812,13.199 h1.52
  text ".Print_Time" at 115.329,13.199 h1.52
  text "TEXAS INSTRUMENTS" at 147.447,13.199 h1.52
M6 Assembly Bottom:
  lines w0.254: 10.147,21.759 177.838,21.759 ; 10.198,16.595 177.838,16.595 ; 45.91,11.265 45.91,16.417 ; 61.709,21.759 61.709,26.924 ; 83.045,21.759 83.045,26.924 ; 115.227,11.43 115.227,26.924 ; 137.808,11.43 177.825,11.43 177.825,26.924 10.147,26.924 10.147,11.43 76.111,11.43 177.838,11.43 177.838,26.924
  text "COMPONENTS MARKED 'DNP' SHOULD NOT BE POPULATED." at 172.568,32.156 h1.52
  text ".VariantName" at 146.05,29.21 h1.52
  text "ASSEMBLY VARIANT:" at 172.441,29.21 h1.52
  text ".VersionControl_RevNumber" at 43.878,23.567 h1.52
  text "SVN REV:" at 56.731,23.567 h1.52
  text ".PCB_Rev" at 70.612,23.567 h1.52
  text "REV:" at 78.016,23.567 h1.52
  text ".PRJ_Number" at 99.466,23.567 h1.52
  text "BOARD #:" at 113.322,23.567 h1.52
  text "PCB VIEWED FROM BOTTOM SIDE" at 176.225,23.567 h1.52
  text "IGNORE ->" at 82.292,18.428 h1.52
  text "TEXAS INSTRUMENTS" at 40.551,13.187 h1.52
  text ".Print_Time" at 72.669,13.187 h1.52
  text ".Print_Date" at 91.186,13.187 h1.52
  text "GENERATED    :" at 113.271,13.187 h1.52
  text ".plot_File_Name" at 155.766,13.187 h1.52
  text "PLOT NAME =" at 176.225,13.187 h1.52
M9 Title Sheet:
  drawing of 57 lines, arcs and shapes, not listed
  text "1" at 36.369,243.091 h1.78
  text "2" at 99.758,243.091 h1.78
  text "3" at 162.988,243.091 h1.78
  text "4" at 226.657,243.091 h1.78
  text "5" at 290.131,243.091 h1.78
  text "6" at 353.758,243.091 h1.78
  text "A" at 6.998,214.058 h1.78
  text "A" at 382.918,214.058 h1.78
  text "B" at 6.998,153.606 h1.78
  text "B" at 382.918,153.606 h1.78
  text ".Layer_Name" at 157.226,143.866 h1.52
  text "C" at 6.998,93.281 h1.78
  text "C" at 382.918,93.281 h1.78
  text "PROJECT TITLE:" at 305.702,46.012 h1.14
  text ".PRJ_Title" at 306.972,42.626 h1.78
  text "DESIGNED FOR:" at 305.702,38.367 h1.14
  text ".PRJ_Customer" at 306.972,34.811 h1.78
  text "D" at 6.998,33.084 h1.78
  text "D" at 382.918,33.084 h1.78
  text "FILE NAME:" at 305.702,30.747 h1.14
  text ".PCB_File_Name_No_Path" at 306.972,27.699 h1.78
  text "Texas Instruments (TI) and/or its licensors do not warrant the accuracy or completeness of this specification" at 179.476,23.588 h1.14
  text "ENGINEER:" at 305.702,23.381 h1.14
  text "LAYOUT BY:" at 343.929,23.381 h1.14
  text "or any information contained therein. TI and/or its licensors do not warrant that this design will meet" at 178.334,20.726 h1.14
  text ".PRJ_Engineer" at 306.972,19.444 h1.78
  text ".PCB_Layout" at 345.211,19.444 h1.78
  text "the specifications, will be suitable for your application or fit for any particular purpose, or will operate in" at 178.334,17.865 h1.14
  text "ALTIUM DESIGNER VERSION:" at 343.929,15.507 h1.14
  text "an implementation. TI and/or its licensors do not warrant that the design is production worthy. You should" at 178.334,15.003 h1.14
  text "completely validate and test your design implementation to confirm the system functionality for your application." at 179.476,12.141 h1.14
  text ".print_Scale" at 306.972,12.12 h1.78
  text ".Application_BuildNumber" at 345.211,12.12 h1.78
  text "1" at 36.369,6.871 h1.78
  text "2" at 99.758,6.871 h1.78
  text "3" at 162.988,6.871 h1.78
  text "4" at 226.657,6.871 h1.78
  text "5" at 290.131,6.871 h1.78
  text "6" at 353.758,6.871 h1.78
M10 Fab Notes:
  drawing of 185 lines, arcs and shapes, not listed
  text "DESIGN INFORMATION" at 332.055,190.348 h1.52
  text "MIN. TRACK WIDTH:" at 315.683,185.776 h1.52
  text "8" at 343.527,185.776 h1.52
  text "MIL" at 347.458,185.776 h1.52
  text "MIN. CLEARANCE:" at 315.683,182.423 h1.52
  text "0.2" at 342.003,182.423 h1.52
  text "mm" at 347.458,182.423 h1.52
  text "MIN. VIA PAD SIZE:" at 315.683,179.07 h1.52
  text "24" at 342.766,179.07 h1.52
  text "MIL" at 347.458,179.07 h1.52
  text "0.05mm (2MIL)" at 333.336,175.471 h1.52
  text "MINIMUM ANNULAR RING" at 307.32,175.362 h1.52
  text "EXTERNAL" at 351.319,175.362 h1.52
  text "PER" at 312.4,172.364 h1.52
  text "IPC-D-275 CLASS 2 LEVEL C" at 317.988,172.364 h1.52
  text "MIL, HOLES" at 355.789,169.512 h1.52
  text "+/-" at 345.821,169.494 h1.52
  text "+/-" at 367.513,169.494 h1.52
  text "REGISTRATION TOLERANCES:" at 307.32,169.367 h1.52
  text "METAL" at 337.795,169.367 h1.52
  text "5" at 352.43,169.367 h1.52
  text "3" at 373.588,169.367 h1.52
  text "MIL" at 376.541,169.367 h1.52
  text "MATERIAL:" at 305.421,164.047 h1.52
  text "FR-4 High Tg" at 330.477,160.482 h1.52
  text "FR-408" at 316.115,160.265 h1.52
  text "X" at 326.579,160.265 h1.52
  text "OTHER" at 353.91,160.265 h1.52
  text "62 MIL (1.6mm) +/-10%" at 324.245,156.132 h1.52
  text "THICKNESS:" at 307.32,156.023 h1.52
  text "X" at 320.99,156.023 h1.52
  text "OTHER" at 356.882,156.023 h1.52
  text "TOLERANCE:" at 307.32,152.01 h1.52
  text "X" at 328.639,152.01 h1.52
  text "ANSI IPC-6012 TYPE 3 CLASS 2" at 333.387,152.01 h1.52
  text "OTHER +/-" at 333.387,148.047 h1.52
  text "BOW & TWIST:" at 307.32,144.06 h1.52
  text "X" at 328.639,144.06 h1.52
  text "ANSI IPC-6012 TYPE 3 CLASS 2" at 333.387,144.06 h1.52
  text ".Layer_Name" at 157.226,141.326 h1.52
  text "OTHER +/-" at 333.387,140.034 h1.52
  text "DRILLING:" at 305.421,136.516 h1.52
  text "REFERENCE:" at 307.32,133.544 h1.52
  text "X" at 323.785,133.544 h1.52
  text "AS SHOWN" at 328.535,133.544 h1.52
  text "X" at 346.671,133.544 h1.52
  text "NC_DRILL FILES" at 350.151,133.544 h1.52
  text "PTH MIN COPPER THICKNESS:" at 307.32,129.531 h1.52
  text "X" at 341.616,129.531 h1.52
  text "1MIL" at 345.096,129.531 h1.52
  text "OTHER" at 357.72,129.531 h1.52
  text "BOARD FINISH:" at 305.421,125.492 h1.52
  text "SILKSCREEN:" at 309.364,122.495 h1.52
  text "X" at 333.463,122.495 h1.52
  text "TOP" at 336.663,122.495 h1.52
  text "X" at 346.417,122.495 h1.52
  text "BOTTOM" at 349.643,122.495 h1.52
  text "SILKSCREEN COLOR:" at 310.634,118.26 h1.52
  text "X" at 333.436,118.253 h1.52
  text "WHITE" at 336.663,118.253 h1.52
  text "OTHER" at 349.643,118.253 h1.52
  text "SOLDER RESIST COLOR:" at 309.364,113.935 h1.52
  text "GREEN" at 327.011,109.892 h1.52
  text "BLUE" at 342.023,109.892 h1.52
  text "OTHER" at 355.688,109.892 h1.52
  text "X" at 323.785,109.644 h1.52
  text "IMMERSION GOLD (ENIG)" at 332.371,105.103 h1.52
  text "ENEPIG" at 366.344,105.02 h1.52
  text "SURFACE FINISH:" at 305.421,104.994 h1.52
  text "X" at 327.622,104.994 h1.52
  text "IMM. TIN/SILVER OR EQUIV" at 313.792,101.007 h1.52
  text "OTHER" at 350.151,101.007 h1.52
  text "ARRAY/PANEL:" at 305.421,96.46 h1.52
  text "CUT AND TRIM PER MECH LAYER 1" at 332.371,96.351 h1.52
  text "N.C. ROUTE" at 332.371,92.498 h1.52
  text "X" at 349.617,92.498 h1.52
  text "V. SCORE" at 354.367,92.498 h1.52
  text "CERTIFICATION:" at 305.421,89.018 h1.52
  text "MATERIALS AND WORKMANSHIP FOR ALL PCBS" at 323.836,89.018 h1.52
  text "TO MEET OR EXCEED THE REQUIREMENTS OF:" at 323.836,86.529 h1.52
  text "X" at 314.349,83.061 h1.52
  text "ANSI IPC-A-600F CLASS ->" at 317.88,83.061 h1.52
  text "X" at 359.512,83.061 h1.52
  text "2" at 362.533,83.061 h1.52
  text "1" at 354.532,83.023 h1.52
  text "3" at 371.525,83.023 h1.52
  text "X" at 314.402,79.01 h1.52
  text "UL 94V-0" at 317.88,79.01 h1.52
  text "X" at 335.026,79.01 h1.52
  text "RoHS" at 338.505,79.01 h1.52
  text "OTHER" at 354.873,79.01 h1.52
  text "PER ORDER" at 364.958,79.01 h1.52
  text "ADDITIONAL REQUIREMENTS:" at 305.193,75.302 h1.52
  text "MICROSECTION:" at 307.092,72.381 h1.52
  text "YES" at 330.098,72.381 h1.52
  text "REQUIRED" at 352.208,68.542 h1.52
  text "NONE" at 340.486,68.469 h1.52
  text "X" at 348.982,68.469 h1.52
  text "PER ORDER" at 367.245,68.469 h1.52
  text "BARE BOARD ELEC. TEST:" at 307.092,68.342 h1.52
  text "MANUFACTURER'S UL:" at 307.092,64.354 h1.52
  text "METAL" at 349.422,64.373 h1.52
  text "X" at 358.953,64.364 h1.52
  text "SILK" at 362.419,64.373 h1.52
  text "RAIL" at 336.702,64.245 h1.52
M11 Gerber Information:
  lines w0.254: 10.16,16.607 177.8,16.607 ; 10.16,21.772 177.851,21.772 ; 10.16,26.937 10.16,11.443 111.887,11.443 177.851,11.443 177.851,26.937 10.173,26.937 10.173,11.443 50.19,11.443 ; 72.771,11.443 72.771,26.937 ; 104.953,21.772 104.953,26.937 ; 126.289,21.772 126.289,26.937 ; 142.088,11.278 142.088,16.43
  text "ALL ARTWORK VIEWED FROM TOP SIDE" at 11.773,23.58 h1.52
  text "BOARD #:" at 74.676,23.58 h1.52
  text ".PRJ_Number" at 88.532,23.58 h1.52
  text "REV:" at 109.982,23.58 h1.52
  text ".PCB_Rev" at 117.386,23.58 h1.52
  text "SVN REV:" at 131.267,23.58 h1.52
  text ".VersionControl_RevNumber" at 144.12,23.58 h1.52
  text "LAYER NAME =" at 11.773,18.428 h1.52
  text "PLOT NAME =" at 11.773,13.199 h1.52
  text ".plot_File_Name" at 32.233,13.199 h1.52
  text "GENERATED    :" at 74.727,13.199 h1.52
  text ".Print_Date" at 96.812,13.199 h1.52
  text ".Print_Time" at 115.329,13.199 h1.52
  text "TEXAS INSTRUMENTS" at 147.447,13.199 h1.52
M12 Stackup:
  lines w0.152: 305.105,221.59 369.875,221.59 ; 305.105,224.241 369.875,224.241 ; 303.581,209.271 ccw(c304.444,209.271) 304.444,208.407 370.535,208.407 ccw(c370.535,209.271) 371.399,209.271 371.399,227.203 ccw(c370.535,227.203) 370.535,228.067 304.444,228.067 ccw(c304.444,227.203) 303.581,227.203 303.581,209.271
  text "The Stackup Legend below this is static." at 311.34,232.118 h1.52
  text "If you change the stackup, update the Legend." at 311.594,229.832 h1.52
  text "Layer Stack Up Detail for: Ref_Design.PcbDoc" at 305.105,225.072 h1.45
  text "Layer" at 305.105,223.251 h0.61
  text "Gerber" at 327.858,223.251 h0.61
  text "Copper" at 342.172,223.251 h0.61
  text "Dielectric" at 357.481,223.251 h0.61
  text "Name" at 305.105,222.032 h0.61
  text "Document" at 327.858,222.032 h0.61
  text "Thickness" at 342.172,222.032 h0.61
  text "Material" at 357.481,222.032 h0.61
  text "Top Solder Mask" at 305.105,219.67 h0.86
  text "(.GTS)" at 327.858,219.67 h0.86
  text "Solder Resist" at 357.481,219.67 h0.86
  text ".Layer_Name" at 284.988,218.186 h1.52
  text "Top Layer" at 305.105,217.213 h0.86
  text "(.GTL)" at 327.858,217.213 h0.86
  text "1.4mil" at 342.172,217.213 h0.86
  text "FR-4" at 357.481,215.984 h0.86
  text "Bottom Layer" at 305.105,214.755 h0.86
  text "(.GBL)" at 327.858,214.755 h0.86
  text "1.4mil" at 342.172,214.755 h0.86
  text "Bottom Solder Mask" at 305.105,212.298 h0.86
  text "(.GBS)" at 327.858,212.298 h0.86
  text "Solder Resist" at 357.481,212.298 h0.86
M13 Component Bodies Top:
  text ".Layer_Name" at 157.226,138.786 h1.52
M14 Component Bodies Bottom:
  text ".Layer_Name" at 157.226,136.246 h1.52
M15 Courtyards Top:
  text ".Layer_Name" at 157.226,133.706 h1.52
M16 Courtyards Bottom:
  text ".Layer_Name" at 157.226,131.166 h1.52
Drill Drawing:
  text ".Layer_Name" at 157.226,105.766 h1.52

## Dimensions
145.11,143.358 to 151.917,158.471 on M2 Board Dimensions
28.677,143.358 to 20.218,169.037 on M2 Board Dimensions
125.679,61.646 to 151.917,58.649 on M2 Board Dimensions
20.218,58.649 to 48.971,60.96 on M2 Board Dimensions
133.68,143.358 to 145.11,143.358 on M2 Board Dimensions
28.677,143.358 to 40.107,143.358 on M2 Board Dimensions
17.577,29.807 to 42.977,29.807 on M2 Board Dimensions
75.844,72.492 to 99.212,72.492 on M2 Board Dimensions
99.212,97.13 to 99.212,72.492 on M2 Board Dimensions
99.72,71.984 to 125.679,61.646 on M2 Board Dimensions
48.971,60.96 to 75.286,71.984 on M2 Board Dimensions
48.971,60.96 to 125.679,61.646 on M2 Board Dimensions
